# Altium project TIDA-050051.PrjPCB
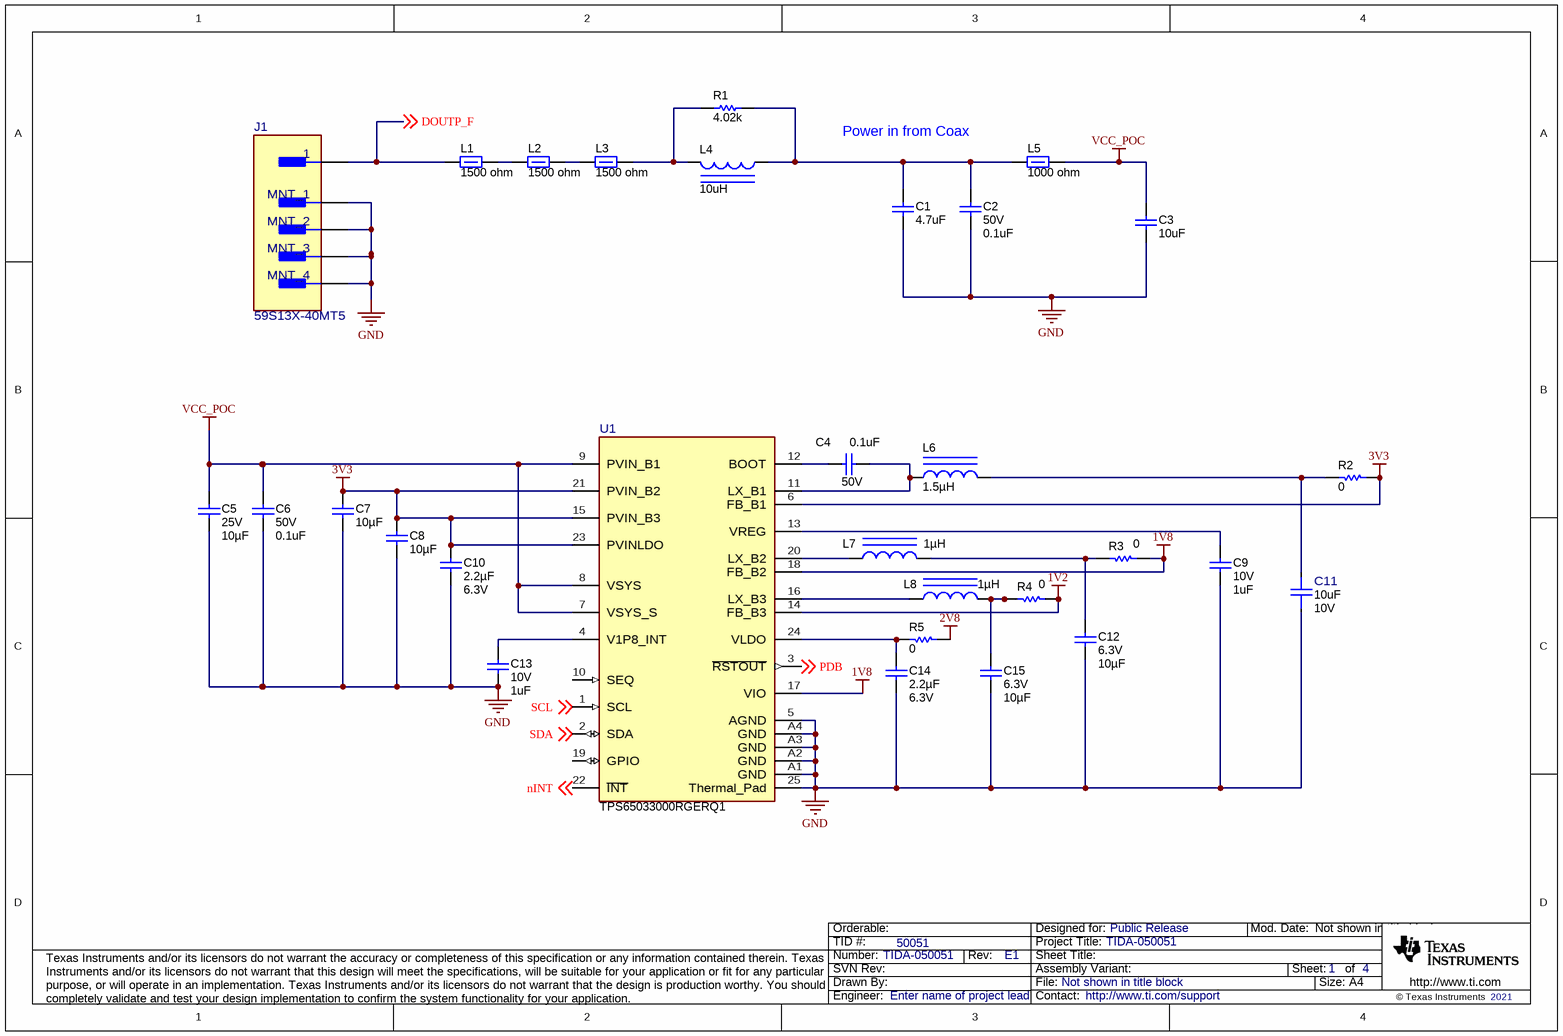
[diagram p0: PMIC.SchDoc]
CopyrightYear: 2021; PCB_Layout: Who did the Layout?; PCB_Rev: E1; PRJ_Customer: Public Release; PRJ_Engineer: Enter name of project lead; PRJ_Number: TIDA-050051; PRJ_Title: TIDA-050051; SCH_Rev: E1; TechSupport: http://www.ti.com/support; TID: 50051
4 sheets, 109 parts. Net scope: global (net labels, ports and power ports of the same name join across sheets).
Board file: TIDA-050051.PcbDoc
Sheets:
  PMIC.SchDoc
  Serializer.SchDoc
  Imager.SchDoc
  Hardware.SchDoc

## Sheet PMIC.SchDoc
size A4; Date: Not shown in title block; ApprovedBy: Not shown in title block; CheckedBy: Not shown in title block; Author: Not shown in title block; CompanyName: Not shown in title block; Engineer: Not shown in title block; Organization: Not shown in title block; Address1: Not shown in title block; Address2: Not shown in title block; Address3: Not shown in title block; Address4: Not shown in title block; DocumentNumber: 1; Revision: Use project parameter SCH_Rev; SheetNumber: 1; SheetTotal: 4; PageSetup: Record=PageOptions¦CenterHorizontal=True¦CenterVertical=True¦PrintScale=1.00¦XCorrection=1.00¦YCorrection=1.00¦PrintKind=0¦BorderSize=5000000¦LeftOffset=0¦BottomOffset=0¦Orientation=2¦PaperLength=1000¦PaperWidth=1000¦Scale=100¦PaperSource=15¦PrintQuality=600¦MediaType=1¦DitherType=10¦PaperKind=Letter¦PrintScaleMode=1

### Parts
C1  ValueDisplayed: 4.7uF  [0805_HV]  (hidden comment: Capacitor)
C2  VDC_V: 50V  ValueDisplayed: 0.1uF  [0402]  (hidden comment: CGA2B3X7R1H104M050BB)
C3  ValueDisplayed: 10uF  [1206_190]  (hidden comment: C3216X7R1E106M160AE)
C4  VDC_V: 50V  ValueDisplayed: 0.1uF  [0402]  (hidden comment: CGA2B3X7R1H104M050BB)
C5  VDC_V: 25V  ValueDisplayed: 10µF  [1206_180]  (hidden comment: C1206C106J3RACAUTO)
C6  VDC_V: 50V  ValueDisplayed: 0.1uF  [0402]  (hidden comment: CGA2B3X7R1H104M050BB)
C7  Cap_F: 10µF  [0603S]  (hidden comment: GRM188Z71A106KA73D)
C8  Cap_F: 10µF  [0603S]  (hidden comment: GRM188Z71A106KA73D)
C9  VDC_V: 10V  ValueDisplayed: 1uF  [0603S]  (hidden comment: LMK107B7105KAHT)
C10  Cap_F: 2.2µF  VDC_V: 6.3V  [0603S]  (hidden comment: GCM188R70J225KE22D)
C11  ValueDisplayed: 10uF  VDC_V: 10V  [FP-CGA4J3X7S1A106K125AE_0805-MFG]  (hidden comment: CGA4J3X7S1A106K125AE)
C12  VDC_V: 6.3V  ValueDisplayed: 10µF  [0805_HV1]  (hidden comment: JMJ212CB7106KGHT)
C13  VDC_V: 10V  ValueDisplayed: 1uF  [0603S]  (hidden comment: LMK107B7105KAHT)
C14  Cap_F: 2.2µF  VDC_V: 6.3V  [0603S]  (hidden comment: GCM188R70J225KE22D)
C15  VDC_V: 6.3V  ValueDisplayed: 10µF  [0805_HV1]  (hidden comment: JMJ212CB7106KGHT)
J1  59S13X-40MT5  [FP-59S13X-40MT5_FAKRA_HF_STR_PLUG-MFG]
L1  value 1500 ohm  [0603L]  (hidden comment: BLM18HE152SN1D)
L2  value 1500 ohm  [0603L]  (hidden comment: BLM18HE152SN1D)
L3  value 1500 ohm  [0603L]  (hidden comment: BLM18HE152SN1D)
L4  ValueDisplayed: 10uH  [LQH3NPZ_JR]  (hidden comment: LQH3NPZ100MJRL)
L5  value 1000 ohm  [0603L]  (hidden comment: BLM18AG102SN1D)
L6  ValueDisplayed: 1.5µH  [TFM201610ALMA]  (hidden comment: TFM201610ALMA1R5MTAA)
L7  ValueDisplayed: 1µH  [TFM201610ALMA]  (hidden comment: TFM201610ALMA1R0MTAA)
L8  ValueDisplayed: 1µH  [TFM201610ALMA]  (hidden comment: TFM201610ALMA1R0MTAA)
R1  ValueDisplayed: 4.02k  [0603L]  (hidden comment: CRCW06034K02FKEA)
R2  ValueDisplayed: 0  [0402S]  (hidden comment: Resistor)
R3  ValueDisplayed: 0  [0402S]  (hidden comment: Resistor)
R4  ValueDisplayed: 0  [0402S]  (hidden comment: Resistor)
R5  ValueDisplayed: 0  [0402S]  (hidden comment: Resistor)
U1  TPS65033000RGERQ1  [RGE0024K-MFG]

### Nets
1V2: R4.2 U1.14(FB_B3)
1V8: R3.2 U1.17(VIO) U1.18(FB_B2)
2V8: R5.2
3V3: C7.1 C8.1 C10.1 R2.2 U1.6(FB_B1) U1.15(PVIN_B3) U1.21(PVIN_B2) U1.23(PVINLDO)
GND: C1.2 C2.2 C3.2 C5.2 C6.2 C7.2 C8.2 C9.1 C10.2 C11.1 C12.2 C13.2 C14.2 C15.2 J1.2(MNT_1) J1.3(MNT_2) J1.4(MNT_3) J1.5(MNT_4) U1.5(AGND) U1.25(Thermal_Pad) U1.A1(GND) U1.A2(GND) U1.A3(GND) U1.A4(GND)
VCC_POC: C3.1 C5.1 C6.1 L5.2 U1.7(VSYS_S) U1.8(VSYS) U1.9(PVIN_B1)
DOUTP_F: J1.1 L1.1 ; off-sheet DOUTP_F
nINT: U1.22(~{INT}) ; off-sheet nINT
PDB: U1.3(~{RSTOUT}) ; off-sheet PDB
SCL: U1.1(SCL) ; off-sheet SCL
SDA: U1.2(SDA) ; off-sheet SDA
NetC1_1: C1.1 C2.1 L4.1 L5.1 R1.1
NetC4_1: C4.1 L6.1 U1.11(LX_B1)
NetC4_2: C4.2 U1.12(BOOT)
NetC9_2: C9.2 U1.13(VREG)
NetC11_2: C11.2 L6.2 R2.1
NetC12_1: C12.1 L7.2 R3.1
NetC13_1: C13.1 U1.4(V1P8_INT)
NetC14_1: C14.1 R5.1 U1.24(VLDO)
NetC15_1: C15.1 L8.2 R4.1
NetL1_2: L1.2 L2.1
NetL2_2: L2.2 L3.1
NetL3_2: L3.2 L4.2 R1.2
NetL7_1: L7.1 U1.20(LX_B2)
NetL8_1: L8.1 U1.16(LX_B3)

Not connected (* = marked no-connect by the designer): U1 10(SEQ) 19(GPIO)

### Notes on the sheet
- (near L5) Power in from Coax

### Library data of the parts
C1 = CMP-0007870-2: CAP, CERM, 4.7 uF, 25 V, +/- 10%, X7R, 0805; PartNumber: C2012X7R1E475K125AB; Manufacturer: TDK; Polarized: N; Value: 4.7uF; U/M: EA; Cap_F: 4.7µF; Value1: Unknown; VDC_V: 25V; TaMin_C: -55°C; TaMax_C: 125°C; Cap_Case: 0805; SizeArea_mm2: 2.5; SizeAreaWB_mm2: 6.75; SizeX_mm: 2; SizeY_mm: 1.25; SizeZ_mm: 1.45; AEC Category: Q200
C2 C4 C6 = CMP-0006326-2: CAP, CERM, 0.1 uF, 50 V, +/- 20%, X7R, AEC-Q200 Grade 1, 0402; Manufacturer: TDK; TaMin_C: -55°C; Polarized: N; SizeAreaWB_mm2: 3; Value1: Unknown; U/M: EA; Value: 0.1uF; TaMax_C: 125°C; SizeZ_mm: 0.6; SizeX_mm: 1; SizeY_mm: 0.5; CompType: Capacitor; AEC Qualified: Y; Cap_F: 100nF; AEC Category: Q200
C3 = CMP-0008692-2: CAP, CERM, 10 uF, 25 V, +/- 20%, X7R, 1206_190; Manufacturer: TDK; Polarized: N; Value: 10uF; U/M: EA; Cap_F: 10µF; Value1: Unknown; VDC_V: 25V; TaMin_C: -55°C; TaMax_C: 125°C; Cap_Case: 1206; SizeArea_mm2: 5.12; SizeAreaWB_mm2: 10.92; SizeX_mm: 3.2; SizeY_mm: 1.6; SizeZ_mm: 1.9; AEC Category: Q200
C5 = CMP-0081062-1: CAP, CERM, 10 µF, 25 V,+/- 5%, X7R, AEC-Q200 Grade 1, 1206; Manufacturer: Kemet; TaMin_C: -55°C; Polarized: N; SizeAreaWB_mm2: 10.92; U/M: EA; Value: 10uF; TaMax_C: 125°C; SizeZ_mm: 1.8; SizeX_mm: 3.2; SizeY_mm: 1.6; SizeArea_mm2: 5.12; AEC Qualified: Y; AEC Grade: 1; AEC Category: Q200
C7 C8 = CMP-0087107-2: Chip Multilayer Ceramic Capacitors for General Purpose; Manufacturer: Murata; Tolerance_%: 10%; VDC_V: 10V; TempCo: 15%; SizeZ_mm: 1mm; AEC Qualified: No
C9 C13 = CMP-0007505-4: CAP, CERM, 1 uF, 10 V, +/- 10%, X7R, AEC-Q200 Grade 1, 0603; Manufacturer: Taiyo Yuden; TaMin_C: -55°C; Polarized: N; SizeAreaWB_mm2: 4.68; Value1: Unknown; U/M: EA; Value: 1uF; TaMax_C: 125°C; SizeZ_mm: 1; SizeX_mm: 1.6; SizeY_mm: 0.8; Cap_Case: 0603; SizeArea_mm2: 1.28; AEC Qualified: Y; Cap_F: 1µF; AEC Category: Q200
C10 C14 = CMP-0007134-5: CAP, CERM, 2.2 uF, 6.3 V, +/- 10%, X7R, AEC-Q200 Grade 1, 0603; Manufacturer: MuRata; SizeAreaWB_mm2: 4.68; Value1: Unknown; Polarized: N; AEC Qualified: Y; SizeX_mm: 1.6; SizeZ_mm: 1; SizeY_mm: 0.8; U/M: EA; TaMin_C: -55°C; Value: 2.2uF; Cap_Case: 0603; AEC Category: Q200; TaMax_C: 125°C; SizeArea_mm2: 1.28
C11 = CMP-0089543-1: 10µF ±10% 10V Ceramic Capacitor X7S 0805 (2012 Metric); Manufacturer: TDK; TempCo: 22%; SizeZ_mm: 1.5mm; AEC Qualified: Yes; AEC Grade: Grade 1
C12 C15 = CMP-0081188-1: CAP, CERM, 10 µF, 6.3 V,+/- 10%, X7R, AEC-Q200 Grade 1, 0805; Manufacturer: Taiyo Yuden; TaMin_C: -55°C; Polarized: N; SizeAreaWB_mm2: 6.75; U/M: EA; Value: 10uF; TaMax_C: 125°C; SizeZ_mm: 1.45; SizeX_mm: 2; SizeY_mm: 1.25; Cap_Case: 0805; SizeArea_mm2: 2.5; AEC Qualified: Y; AEC Category: Q200; AEC Grade: 1
J1 = CMP-0092218-1: FAKRA-HF STRAIGHT PLUG for PCB; Manufacturer: Rosenberger; AEC Qualified: No; ContactFinish: Gold,Tin; Shrouded: true; Dielectric Material: HTN; Voltage_V: 335V; Current_A: 1A; Impedance: 50Ω; SizeZ_mm: 15mm; Frequency_Fixed: 6GHz
L1 L2 = CMP-0003349-2: Ferrite Bead, 1500 ohm @ 100 MHz, 0.5 A, 0603; Manufacturer: MuRata; Imax_A: 500mA; DCR_ohm: 0.5; Value1: 0.5 ohm; Value2: 0.5A; ZTyp@100MHz_Ohm: 1.5k; SizeAreaWB_mm2: 4.68; SizeArea_mm2: 1.28; SizeX_mm: 1.6; SizeY_mm: 0.8; SizeZ_mm: 1
L3 = CMP-0003349-2: Ferrite Bead, 1500 ohm @ 100 MHz, 0.5 A, 0603; Manufacturer: MuRata; Value1: 0.5 ohm; Value2: 0.5A; SizeArea_mm2: 1.28; SizeX_mm: 1.6; SizeY_mm: 0.8; SizeZ_mm: 1; Imax_A: 500mA; DCR_ohm: 0.5; SizeAreaWB_mm2: 4.68; ZTyp@100MHz_Ohm: 1.5k
L4 = CMP-0058702-1: Inductor, Wirewound, Ferrite, 10 uH, 0.81 A, 0.288 ohm, AEC-Q200 Grade 1, SMD; Manufacturer: MuRata; Value: 10uH; Ind_H: 10µH; Imax_A: 810mA; Irms: 1.2A @ 40C rise; Isat: 0.81A @ 30% inductance drop; DCR_ohm: 0.288; Value2: 0.81A; SizeAreaWB_mm2: 16; SizeArea_mm2: 9; SizeX_mm: 3; SizeZ_mm: 1.2; AEC Category: Q200; AEC Qualified: Y; AEC Grade: 1
L5 = CMP-0003343-2: Ferrite Bead, 1000 ohm @ 100 MHz, 0.4 A, 0603; Manufacturer: MuRata; Imax_A: 400mA; DCR_ohm: 0.5; Value1: 0.5 ohm; Value2: 0.4A; ZTyp@100MHz_Ohm: 1k; SizeArea_mm2: 1.28; SizeAreaWB_mm2: 4.68; SizeX_mm: 1.6; SizeY_mm: 0.8; SizeZ_mm: 1
L6 = CMP-0081093-1: Inductor, Shielded, Metal Composite, 1.5 µH, 2.3 A, 0.11 ohm, AEC-Q200 Grade 0, SMD; Manufacturer: TDK; Isat: 2.8A @ 30% inductance drop; Irms: 2.3A @ 40C rise; SizeAreaWB_mm2: 7.8; DCR_ohm: 0.11; Value: 1.5uH; Imax_A: 2.3A; SizeZ_mm: 1; SizeX_mm: 2; SizeY_mm: 1.6; SizeArea_mm2: 3.2; AEC Qualified: Y; AEC Grade: 0; AEC Category: Q200
L7 L8 = CMP-0081092-1: Inductor, Shielded, Metal Composite, 1 µH, 3.1 A, 0.06 ohm, AEC-Q200 Grade 0, SMD; Manufacturer: TDK; Isat: 3.3A @ 30% inductance drop; Irms: 3.1A @ 40C rise; SizeAreaWB_mm2: 7.8; DCR_ohm: 0.06; Value: 1uH; Imax_A: 3.1A; SizeZ_mm: 1; SizeX_mm: 2; SizeY_mm: 1.6; SizeArea_mm2: 3.2; AEC Qualified: Y; AEC Grade: 0; AEC Category: Q200
R1 = CMP-0022449-4: RES, 4.02 k, 1%, 0.1 W, AEC-Q200 Grade 0, 0603; Manufacturer: Vishay-Dale; Value: 4.02k; Value_Code: 4k02; Power_W: 100mW; Value2: 0.1W; VDC_V: 75V; TempCo: 100 ppm/C; EIA_Code: E96; AEC Category: Q200; AEC Grade: 0; AEC Qualified: Y; SizeArea_mm2: 1.28; SizeX_mm: 1.6; SizeY_mm: 0.8; SizeZ_mm: 1
R2-R5 = CMP-0027004-2: RES, 0, 5%, 0.063 W, 0402; PartNumber: RC0402JR-070RL; Manufacturer: Yageo America; Value: 0; Value_Code: 0000; Power_W: 63mW; Value2: 0.063W; VDC_V: 50V; TempCo: 200 ppm/C; SizeArea_mm2: 0.5; SizeX_mm: 1; SizeZ_mm: 0.6; EIA_Code: E24; U/M: EA; AEC Category: Q200
U1 = CMP-0092635-1: Highly integrated power management IC for automotive camera modules; Manufacturer: Texas Instruments; Standoff Height: 0mm; AEC Grade: Grade 1; Output Voltage: 2.5-4/0.9-1.9/1.8-3.3V; Nominal Supply Current: 10mA; Max Supply Voltage: 18.3V; Min Supply Voltage: 4V; TaMin_C: -40°C; TaMax_C: +125°C; AEC Qualified: Yes; SizeZ_mm: 1mm; Number Of Outputs: 4; TJmax_C: +150°C

## Sheet Serializer.SchDoc
size A4; Date: Not shown in title block; ApprovedBy: Not shown in title block; CheckedBy: Not shown in title block; Author: Not shown in title block; CompanyName: Not shown in title block; Engineer: Not shown in title block; Organization: Not shown in title block; Address1: Not shown in title block; Address2: Not shown in title block; Address3: Not shown in title block; Address4: Not shown in title block; DocumentNumber: 2; Revision: Use project parameter SCH_Rev; SheetNumber: 2; SheetTotal: 4; PageSetup: Record=PageOptions¦CenterHorizontal=True¦CenterVertical=True¦PrintScale=1.00¦XCorrection=1.00¦YCorrection=1.00¦PrintKind=0¦BorderSize=5000000¦LeftOffset=0¦BottomOffset=0¦Orientation=2¦PaperLength=1000¦PaperWidth=1000¦Scale=100¦PaperSource=15¦PrintQuality=600¦MediaType=1¦DitherType=10¦PaperKind=Letter¦PrintScaleMode=1
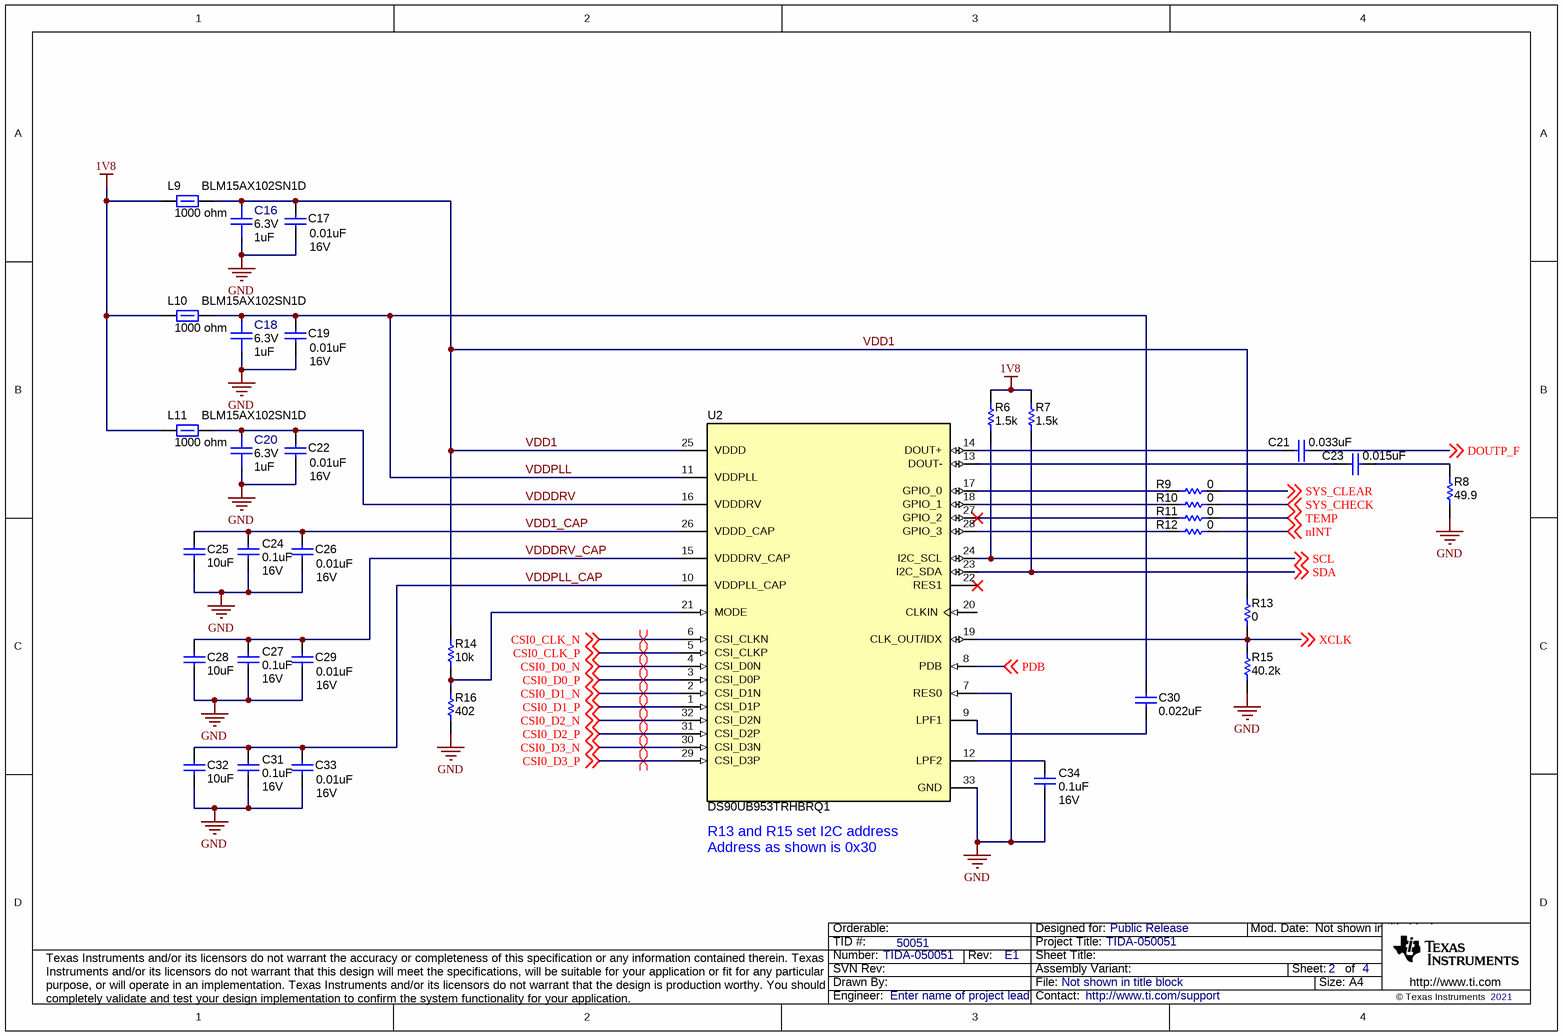
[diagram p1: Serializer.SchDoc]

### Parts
C16  VDC_V: 6.3V  ValueDisplayed: 1uF  [FP-GRT155R70J105KE01D_0402-MFG]  (hidden comment: GRT155R70J105KE01D)
C17  ValueDisplayed: 0.01uF  Value2: 16V  [0402S]  (hidden comment: GRM155R71C103KA01D)
C18  VDC_V: 6.3V  ValueDisplayed: 1uF  [FP-GRT155R70J105KE01D_0402-MFG]  (hidden comment: GRT155R70J105KE01D)
C19  ValueDisplayed: 0.01uF  Value2: 16V  [0402S]  (hidden comment: GRM155R71C103KA01D)
C20  VDC_V: 6.3V  ValueDisplayed: 1uF  [FP-GRT155R70J105KE01D_0402-MFG]  (hidden comment: GRT155R70J105KE01D)
C21  ValueDisplayed: 0.033uF  [0402S]  (hidden comment: CGA2B3X7R1H333K050BB)
C22  ValueDisplayed: 0.01uF  Value2: 16V  [0402S]  (hidden comment: GRM155R71C103KA01D)
C23  ValueDisplayed: 0.015uF  [0402S]  (hidden comment: CGA2B3X7R1H153K050BB)
C24  ValueDisplayed: 0.1uF  Value2: 16V  [0402S]  (hidden comment: 0402YC104KAT2A)
C25  ValueDisplayed: 10uF  [0603S]  (hidden comment: GRM188Z71A106MA73D)
C26  ValueDisplayed: 0.01uF  Value2: 16V  [0402S]  (hidden comment: GRM155R71C103KA01D)
C27  ValueDisplayed: 0.1uF  Value2: 16V  [0402S]  (hidden comment: 0402YC104KAT2A)
C28  ValueDisplayed: 10uF  [0603S]  (hidden comment: GRM188Z71A106MA73D)
C29  ValueDisplayed: 0.01uF  Value2: 16V  [0402S]  (hidden comment: GRM155R71C103KA01D)
C30  ValueDisplayed: 0.022uF  [0402S]  (hidden comment: GRM155R70J223KA01D)
C31  ValueDisplayed: 0.1uF  Value2: 16V  [0402S]  (hidden comment: 0402YC104KAT2A)
C32  ValueDisplayed: 10uF  [0603S]  (hidden comment: GRM188Z71A106MA73D)
C33  ValueDisplayed: 0.01uF  Value2: 16V  [0402S]  (hidden comment: GRM155R71C103KA01D)
C34  ValueDisplayed: 0.1uF  Value2: 16V  [0402S]  (hidden comment: 0402YC104KAT2A)
L9  value 1000 ohm  [0402S]  (hidden comment: BLM15AX102SN1D)
L10  value 1000 ohm  [0402S]  (hidden comment: BLM15AX102SN1D)
L11  value 1000 ohm  [0402S]  (hidden comment: BLM15AX102SN1D)
R6  ValueDisplayed: 1.5k  [0402S]  (hidden comment: CRCW04021K50JNED)
R7  ValueDisplayed: 1.5k  [0402S]  (hidden comment: CRCW04021K50JNED)
R8  value 49.9  [0402L]  (hidden comment: CRCW040249R9FKED)
R9  ValueDisplayed: 0  [0402S]  (hidden comment: CRCW04020000Z0ED)
R10  ValueDisplayed: 0  [0402S]  (hidden comment: CRCW04020000Z0ED)
R11  ValueDisplayed: 0  [0402S]  (hidden comment: CRCW04020000Z0ED)
R12  ValueDisplayed: 0  [0402S]  (hidden comment: CRCW04020000Z0ED)
R13  ValueDisplayed: 0  [0402S]  (hidden comment: CRCW04020000Z0ED)
R14  value 10k  [0402S]  (hidden comment: CRCW040210K0JNED)
R15  ValueDisplayed: 40.2k  [0402S]  (hidden comment: CRCW040240K2FKED)
R16  ValueDisplayed: 402  [0402S]  (hidden comment: CRCW0402402RFKED)
U2  DS90UB953TRHBRQ1  [RHB0032P]

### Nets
1V8: L9.1 L10.1 L11.1 R6.2 R7.2
GND: C16.1 C17.2 C18.1 C19.2 C20.1 C22.2 C24.2 C25.1 C26.2 C27.2 C28.1 C29.2 C31.2 C32.1 C33.2 C34.2 R8.1 R15.1 R16.1 U2.7(RES0) U2.33(GND)
CSI0_CLK_N: U2.6(CSI_CLKN) ; off-sheet CSI0_CLK_N
CSI0_CLK_P: U2.5(CSI_CLKP) ; off-sheet CSI0_CLK_P
CSI0_D0_N: U2.4(CSI_D0N) ; off-sheet CSI0_D0_N
CSI0_D0_P: U2.3(CSI_D0P) ; off-sheet CSI0_D0_P
CSI0_D1_N: U2.2(CSI_D1N) ; off-sheet CSI0_D1_N
CSI0_D1_P: U2.1(CSI_D1P) ; off-sheet CSI0_D1_P
CSI0_D2_N: U2.32(CSI_D2N) ; off-sheet CSI0_D2_N
CSI0_D2_P: U2.31(CSI_D2P) ; off-sheet CSI0_D2_P
CSI0_D3_N: U2.30(CSI_D3N) ; off-sheet CSI0_D3_N
CSI0_D3_P: U2.29(CSI_D3P) ; off-sheet CSI0_D3_P
DOUTP_F: C21.1 ; off-sheet DOUTP_F
nINT: R12.1 ; off-sheet nINT
PDB: U2.8(PDB) ; off-sheet PDB
SCL: R6.1 U2.24(I2C_SCL) ; off-sheet SCL
SDA: R7.1 U2.23(I2C_SDA) ; off-sheet SDA
SYS_CHECK: R10.1 ; off-sheet SYS_CHECK
SYS_CLEAR: R9.1 ; off-sheet SYS_CLEAR
TEMP: R11.1 ; off-sheet TEMP
VDD1: C16.2 C17.1 L9.2 R13.2 R14.2 U2.25(VDDD)
VDD1_CAP: C24.1 C25.2 C26.1 U2.26(VDDD_CAP)
VDDDRV: C20.2 C22.1 L11.2 U2.16(VDDDRV)
VDDDRV_CAP: C27.1 C28.2 C29.1 U2.15(VDDDRV_CAP)
VDDPLL: C18.2 C19.1 C30.1 L10.2 U2.11(VDDPLL)
VDDPLL_CAP: C31.1 C32.2 C33.1 U2.10(VDDPLL_CAP)
XCLK: R13.1 R15.2 U2.19(CLK_OUT/IDX) ; off-sheet XCLK
NetC21_2: C21.2 U2.14(DOUT+)
NetC23_1: C23.1 R8.2
NetC23_2: C23.2 U2.13(DOUT-)
NetC30_2: C30.2 U2.9(LPF1)
NetC34_1: C34.1 U2.12(LPF2)
NetR9_2: R9.2 U2.17(GPIO_0)
NetR10_2: R10.2 U2.18(GPIO_1)
NetR11_2: R11.2 U2.27(GPIO_2)
NetR12_2: R12.2 U2.28(GPIO_3)
NetR14_1: R14.1 R16.2 U2.21(MODE)

Not connected (* = marked no-connect by the designer): U2 20(CLKIN) 22(RES1)*

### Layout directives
differential pair: CSI0_CLK_N, CSI0_CLK_P, CSI0_D0_N, CSI0_D0_P, CSI0_D1_N, CSI0_D1_P, CSI0_D2_N, CSI0_D2_P, CSI0_D3_N, CSI0_D3_P

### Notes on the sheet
- (near U2) R13 and R15 set I2C address
  Address as shown is 0x30

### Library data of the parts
C16 C18 C20 = CMP-0088425-1: 1µF ±10% 6.3V Ceramic Capacitor X7R 0402 (1005 Metric); Manufacturer: Murata; TempCo: 15%; AEC Grade: Grade 1; SizeZ_mm: 0.55mm; AEC Qualified: Yes
C17 C19 C22 C26 C29 C33 = CMP-0006639-2: CAP, CERM, 0.01 uF, 16 V, +/- 10%, X7R, 0402; Manufacturer: MuRata; Polarized: N; Value: 0.01uF; U/M: EA; Cap_F: 10nF; Value1: Unknown; TaMin_C: -55°C; TaMax_C: 125°C; Cap_Case: 0402; AEC Category: Q200; SizeArea_mm2: 0.5; SizeAreaWB_mm2: 3; SizeX_mm: 1; SizeZ_mm: 0.6
C21 = CMP-0006329-2: CAP, CERM, 0.033 uF, 50 V, +/- 10%, X7R, AEC-Q200 Grade 1, 0402; Manufacturer: TDK; Polarized: N; U/M: EA; Cap_F: 33nF; ESR_ohm: 0.098477; Value1: 0.098477 ohm; VDC_V: 50V; IRMS_A: 530.78mA; TaMin_C: -55°C; TaMax_C: 125°C; Cap_Case: 0402; AEC Category: Q200; AEC Grade: 1; AEC Qualified: Y; SizeArea_mm2: 0.5; SizeAreaWB_mm2: 3; SizeZ_mm: 0.6
C23 = CMP-0006327-2: CAP, CERM, 0.015 uF, 50 V, +/- 10%, X7R, AEC-Q200 Grade 1, 0402; Manufacturer: TDK; Polarized: N; U/M: EA; Cap_F: 15nF; ESR_ohm: 0.2162; Value1: 0.2162 ohm; VDC_V: 50V; IRMS_A: 379.389mA; TaMin_C: -55°C; TaMax_C: 125°C; Cap_Case: 0402; SizeArea_mm2: 0.5; SizeAreaWB_mm2: 3; SizeX_mm: 1; SizeZ_mm: 0.6; AEC Category: Q200; AEC Qualified: Y
C24 C27 C31 C34 = CMP-0006201-2: CAP, CERM, 0.1 uF, 16 V, +/- 10%, X7R, 0402; Manufacturer: AVX; Polarized: N; Value: 0.1uF; U/M: EA; Cap_F: 100nF; Value1: Unknown; TaMin_C: -55°C; TaMax_C: 125°C; Cap_Case: 0402; SizeArea_mm2: 0.5; SizeAreaWB_mm2: 3; SizeX_mm: 1; SizeZ_mm: 0.6; AEC Category: Q200
C25 C28 C32 = CMP-0007497-5: CAP, CERM, 10 uF, 10 V, +/- 20%, X7R, 0603; Manufacturer: MuRata; Polarized: N; Value: 10uF; U/M: EA; Cap_F: 10µF; Value1: Unknown; VDC_V: 10V; TaMin_C: -55°C; TaMax_C: 125°C; Cap_Case: 0603; SizeArea_mm2: 1.28; SizeAreaWB_mm2: 4.68; SizeX_mm: 1.6; SizeY_mm: 0.8; SizeZ_mm: 1; AEC Category: Q200
C30 = CMP-0006626-2: CAP, CERM, 0.022 uF, 6.3 V, +/- 10%, X7R, 0402; Manufacturer: MuRata; Polarized: N; U/M: EA; Cap_F: 22nF; Value1: Unknown; VDC_V: 6.3V; TaMin_C: -55°C; TaMax_C: 125°C; Cap_Case: 0402; SizeArea_mm2: 0.5; SizeAreaWB_mm2: 3; SizeX_mm: 1; SizeZ_mm: 0.6; AEC Category: Q200
L9-L11 = CMP-0003316-1: Ferrite Bead, 1000 ohm @ 100 MHz, 0.35 A, 0402; Manufacturer: MuRata; Imax_A: 350mA; DCR_ohm: 0.49; Value1: 0.49 ohm; Value2: 0.35A; ZTyp@100MHz_Ohm: 1k; SizeArea_mm2: 0.5; SizeAreaWB_mm2: 3; SizeX_mm: 1; SizeZ_mm: 0.6
R6 R7 = CMP-0026856-5: RES, 1.5 k, 5%, 0.063 W, AEC-Q200 Grade 0, 0402; Manufacturer: Vishay-Dale; Value: 1.5k; Value_Code: 1k50; Power_W: 63mW; Value2: 0.063W; VDC_V: 50V; TempCo: 200 ppm/C; SizeArea_mm2: 0.5; SizeX_mm: 1; SizeZ_mm: 0.6; EIA_Code: E24; AEC Category: Q200; AEC Qualified: Y; AEC Grade: 0
R8 = CMP-0026404-2: RES, 49.9, 1%, 0.063 W, AEC-Q200 Grade 0, 0402; Manufacturer: Vishay-Dale; Value_Code: 49R9; Power_W: 63mW; Value2: 0.063W; VDC_V: 50V; TempCo: 100 ppm/C; EIA_Code: E96; AEC Category: Q200; AEC Grade: 0; AEC Qualified: Y; SizeArea_mm2: 0.5; SizeX_mm: 1; SizeZ_mm: 0.6
R9-R13 = CMP-0026822-3: RES, 0, 5%, 0.063 W, AEC-Q200 Grade 0, 0402; Manufacturer: Vishay-Dale; Value: 0; Value_Code: 0000; Power_W: 63mW; Value2: 0.063W; VDC_V: 50V; TempCo: 200 ppm/C; SizeArea_mm2: 0.5; SizeX_mm: 1; SizeZ_mm: 0.6; EIA_Code: E24; AEC Category: Q200; AEC Qualified: Y
R14 = CMP-0026825-5: RES, 10 k, 5%, 0.063 W, AEC-Q200 Grade 0, 0402; Manufacturer: Vishay-Dale; Value_Code: 10k0; Power_W: 63mW; Value2: 0.063W; VDC_V: 50V; TempCo: 200 ppm/C; EIA_Code: E24; AEC Category: Q200; AEC Grade: 0; AEC Qualified: Y; SizeArea_mm2: 0.5; SizeX_mm: 1; SizeZ_mm: 0.6
R15 = CMP-0026367-2: RES, 40.2 k, 1%, 0.063 W, AEC-Q200 Grade 0, 0402; Manufacturer: Vishay-Dale; Value: 40.2k; Value_Code: 40k2; Power_W: 63mW; Value2: 0.063W; VDC_V: 50V; TempCo: 100 ppm/C; SizeArea_mm2: 0.5; SizeX_mm: 1; SizeZ_mm: 0.6; EIA_Code: E96; AEC Category: Q200; AEC Qualified: Y; AEC Grade: 0
R16 = CMP-0026366-2: RES, 402, 1%, 0.063 W, AEC-Q200 Grade 0, 0402; Manufacturer: Vishay-Dale; Value: 402; Value_Code: 402R; Power_W: 63mW; Value2: 0.063W; VDC_V: 50V; TempCo: 100 ppm/C; SizeArea_mm2: 0.5; SizeX_mm: 1; SizeZ_mm: 0.6; EIA_Code: E96; AEC Category: Q200; AEC Qualified: Y; AEC Grade: 0
U2 = CMP-0084098-1: 2MP MIPI CSI-2 FPD-Link III Serializer for 2MP/60fps Cameras and RADAR, RHB0032P (VQFN-32); Manufacturer: Texas Instruments; Alternate PartNumber: DS90UB953TRHBTQ1; Rating: Automotive; SizeAreaWB_mm2: 49; SizeArea_mm2: 25; AEC Qualified: Y; AEC Category: Q200; SizeZ_mm: 1; SizeY_mm: 5; CompType: IC

## Sheet Imager.SchDoc
size A4; Date: Not shown in title block; ApprovedBy: Not shown in title block; CheckedBy: Not shown in title block; Author: Not shown in title block; CompanyName: Not shown in title block; Engineer: Not shown in title block; Organization: Not shown in title block; Address1: Not shown in title block; Address2: Not shown in title block; Address3: Not shown in title block; Address4: Not shown in title block; DocumentNumber: 3; Revision: Use project parameter SCH_Rev; SheetNumber: 3; SheetTotal: 4; PageSetup: Record=PageOptions¦CenterHorizontal=True¦CenterVertical=True¦PrintScale=1.00¦XCorrection=1.00¦YCorrection=1.00¦PrintKind=0¦BorderSize=5000000¦LeftOffset=0¦BottomOffset=0¦Orientation=2¦PaperLength=1000¦PaperWidth=1000¦Scale=100¦PaperSource=15¦PrintQuality=600¦MediaType=1¦DitherType=10¦PaperKind=Letter¦PrintScaleMode=1
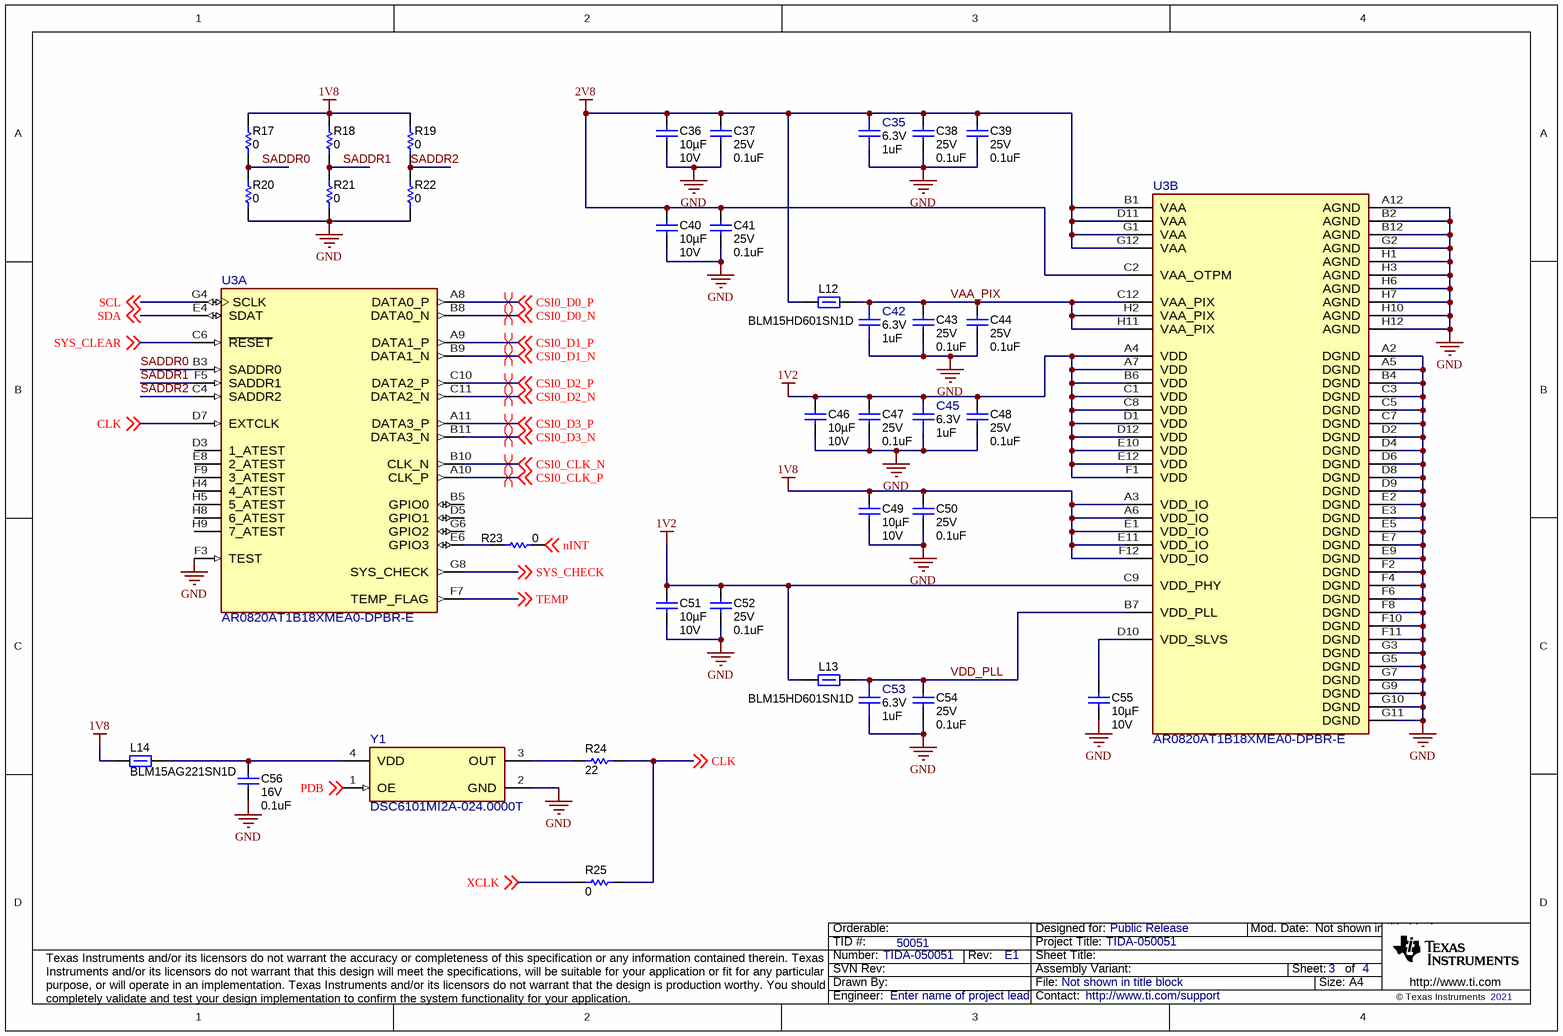
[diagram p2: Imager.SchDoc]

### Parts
C35  VDC_V: 6.3V  ValueDisplayed: 1uF  [FP-GRT155R70J105KE01D_0402-MFG]  (hidden comment: GRT155R70J105KE01D)
C36  Cap_F: 10µF  VDC_V: 10V  [0805_HV1]  (hidden comment: GCJ21BR71A106KE01L)
C37  VDC_V: 25V  ValueDisplayed: 0.1uF  [0402L]  (hidden comment: GRM155R71E104KE14D)
C38  VDC_V: 25V  ValueDisplayed: 0.1uF  [0402L]  (hidden comment: GRM155R71E104KE14D)
C39  VDC_V: 25V  ValueDisplayed: 0.1uF  [0402L]  (hidden comment: GRM155R71E104KE14D)
C40  Cap_F: 10µF  VDC_V: 10V  [0805_HV1]  (hidden comment: GCJ21BR71A106KE01L)
C41  VDC_V: 25V  ValueDisplayed: 0.1uF  [0402L]  (hidden comment: GRM155R71E104KE14D)
C42  VDC_V: 6.3V  ValueDisplayed: 1uF  [FP-GRT155R70J105KE01D_0402-MFG]  (hidden comment: GRT155R70J105KE01D)
C43  VDC_V: 25V  ValueDisplayed: 0.1uF  [0402L]  (hidden comment: GRM155R71E104KE14D)
C44  VDC_V: 25V  ValueDisplayed: 0.1uF  [0402L]  (hidden comment: GRM155R71E104KE14D)
C45  VDC_V: 6.3V  ValueDisplayed: 1uF  [FP-GRT155R70J105KE01D_0402-MFG]  (hidden comment: GRT155R70J105KE01D)
C46  Cap_F: 10µF  VDC_V: 10V  [0805_HV1]  (hidden comment: GCJ21BR71A106KE01L)
C47  VDC_V: 25V  ValueDisplayed: 0.1uF  [0402L]  (hidden comment: GRM155R71E104KE14D)
C48  VDC_V: 25V  ValueDisplayed: 0.1uF  [0402L]  (hidden comment: GRM155R71E104KE14D)
C49  Cap_F: 10µF  VDC_V: 10V  [0805_HV1]  (hidden comment: GCJ21BR71A106KE01L)
C50  VDC_V: 25V  ValueDisplayed: 0.1uF  [0402L]  (hidden comment: GRM155R71E104KE14D)
C51  Cap_F: 10µF  VDC_V: 10V  [0805_HV1]  (hidden comment: GCJ21BR71A106KE01L)
C52  VDC_V: 25V  ValueDisplayed: 0.1uF  [0402L]  (hidden comment: GRM155R71E104KE14D)
C53  VDC_V: 6.3V  ValueDisplayed: 1uF  [FP-GRT155R70J105KE01D_0402-MFG]  (hidden comment: GRT155R70J105KE01D)
C54  VDC_V: 25V  ValueDisplayed: 0.1uF  [0402L]  (hidden comment: GRM155R71E104KE14D)
C55  Cap_F: 10µF  VDC_V: 10V  [0805_HV1]  (hidden comment: GCJ21BR71A106KE01L)
C56  VDC_V: 16V  ValueDisplayed: 0.1uF  [0402S]  (hidden comment: GCM155R71C104KA55D)
L12  BLM15HD601SN1D  [0402S]
L13  BLM15HD601SN1D  [0402S]
L14  BLM15AG221SN1D  [0402S]
R17  ValueDisplayed: 0  [0402S]  (hidden comment: CRCW04020000Z0ED)
R18  ValueDisplayed: 0  [0402S]  (hidden comment: CRCW04020000Z0ED)
R19  ValueDisplayed: 0  [0402S]  (hidden comment: CRCW04020000Z0ED)
R20  ValueDisplayed: 0  [0402S]  (hidden comment: CRCW04020000Z0ED)
R21  ValueDisplayed: 0  [0402S]  (hidden comment: CRCW04020000Z0ED)
R22  ValueDisplayed: 0  [0402S]  (hidden comment: CRCW04020000Z0ED)
R23  ValueDisplayed: 0  [0402S]  (hidden comment: CRCW04020000Z0ED)
R24  ValueDisplayed: 22  [0402S]  (hidden comment: ERJ-2GEJ220X)
R25  ValueDisplayed: 0  [0402S]  (hidden comment: ERJ-2GE0R00X)
U3  AR0820AT1B18XMEA0-DPBR-E  [FP-AR0820AT1B18XMEA0-DPBR-E_iBGA95-MFG]  (parts A,B of 2)
Y1  DSC6101MI2A-024.0000T  [FP-DSC6101MI2A-024.0000T_VFLGA4-0]

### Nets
1V2: C45.2 C46.1 C47.1 C48.1 C51.1 C52.1 L13.1 U3.A4(VDD) U3.A7(VDD) U3.B6(VDD) U3.C1(VDD) U3.C8(VDD) U3.C9(VDD_PHY) U3.D1(VDD) U3.D12(VDD) U3.E10(VDD) U3.E12(VDD) U3.F1(VDD)
1V8: C49.1 C50.1 L14.1 R17.2 R18.2 R19.2 U3.A3(VDD_IO) U3.A6(VDD_IO) U3.E1(VDD_IO) U3.E11(VDD_IO) U3.F12(VDD_IO)
2V8: C35.2 C36.1 C37.1 C38.1 C39.1 C40.1 C41.1 L12.1 U3.B1(VAA) U3.C2(VAA_OTPM) U3.D11(VAA) U3.G1(VAA) U3.G12(VAA)
GND: C35.1 C36.2 C37.2 C38.2 C39.2 C40.2 C41.2 C42.1 C43.2 C44.2 C45.1 C46.2 C47.2 C48.2 C49.2 C50.2 C51.2 C52.2 C53.1 C54.2 C55.2 C56.2 R20.1 R21.1 R22.1 U3.A2(DGND) U3.A5(DGND) U3.A12(AGND) U3.B2(AGND) U3.B4(DGND) U3.B12(AGND) U3.C3(DGND) U3.C5(DGND) U3.C7(DGND) U3.D2(DGND) U3.D4(DGND) U3.D6(DGND) U3.D8(DGND) U3.D9(DGND) U3.E2(DGND) U3.E3(DGND) U3.E5(DGND) U3.E7(DGND) U3.E9(DGND) U3.F2(DGND) U3.F3(TEST) U3.F4(DGND) U3.F6(DGND) U3.F8(DGND) U3.F10(DGND) U3.F11(DGND) U3.G2(AGND) U3.G3(DGND) U3.G5(DGND) U3.G7(DGND) U3.G9(DGND) U3.G10(DGND) U3.G11(DGND) U3.H1(AGND) U3.H3(AGND) U3.H6(AGND) U3.H7(AGND) U3.H10(AGND) U3.H12(AGND) Y1.2(GND)
CLK: R24.2 R25.2 U3.D7(EXTCLK) ; off-sheet CLK
CSI0_CLK_N: U3.B10(CLK_N) ; off-sheet CSI0_CLK_N
CSI0_CLK_P: U3.A10(CLK_P) ; off-sheet CSI0_CLK_P
CSI0_D0_N: U3.B8(DATA0_N) ; off-sheet CSI0_D0_N
CSI0_D0_P: U3.A8(DATA0_P) ; off-sheet CSI0_D0_P
CSI0_D1_N: U3.B9(DATA1_N) ; off-sheet CSI0_D1_N
CSI0_D1_P: U3.A9(DATA1_P) ; off-sheet CSI0_D1_P
CSI0_D2_N: U3.C11(DATA2_N) ; off-sheet CSI0_D2_N
CSI0_D2_P: U3.C10(DATA2_P) ; off-sheet CSI0_D2_P
CSI0_D3_N: U3.B11(DATA3_N) ; off-sheet CSI0_D3_N
CSI0_D3_P: U3.A11(DATA3_P) ; off-sheet CSI0_D3_P
nINT: R23.1 ; off-sheet nINT
PDB: Y1.1(OE) ; off-sheet PDB
SADDR0: R17.1 R20.2 U3.B3(SADDR0)
SADDR1: R18.1 R21.2 U3.F5(SADDR1)
SADDR2: R19.1 R22.2 U3.C4(SADDR2)
SCL: U3.G4(SCLK) ; off-sheet SCL
SDA: U3.E4(SDAT) ; off-sheet SDA
SYS_CHECK: U3.G8(SYS_CHECK) ; off-sheet SYS_CHECK
SYS_CLEAR: U3.C6(~{RESET}) ; off-sheet SYS_CLEAR
TEMP: U3.F7(TEMP_FLAG) ; off-sheet TEMP
VAA_PIX: C42.2 C43.1 C44.1 L12.2 U3.C12(VAA_PIX) U3.H2(VAA_PIX) U3.H11(VAA_PIX)
VDD_PLL: C53.2 C54.1 L13.2 U3.B7(VDD_PLL)
XCLK: R25.1 ; off-sheet XCLK
NetC55_1: C55.1 U3.D10(VDD_SLVS)
NetC56_1: C56.1 L14.2 Y1.4(VDD)
NetR23_2: R23.2 U3.E6(GPIO3)
NetR24_1: R24.1 Y1.3(OUT)

Not connected (* = marked no-connect by the designer): U3 B5(GPIO0) D3(1_ATEST) D5(GPIO1) E8(2_ATEST) F9(3_ATEST) G6(GPIO2) H4(4_ATEST) H5(5_ATEST) H8(6_ATEST) H9(7_ATEST)

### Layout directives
differential pair: CSI0_CLK_N, CSI0_CLK_P, CSI0_D0_N, CSI0_D0_P, CSI0_D1_N, CSI0_D1_P, CSI0_D2_N, CSI0_D2_P, CSI0_D3_N, CSI0_D3_P

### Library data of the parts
C35 C42 C45 C53 = CMP-0088425-1: as C16 on sheet Serializer
C36 C40 C46 C49 C51 C55 = CMP-0079153-1: CAP, CERM, 10 µF, 10 V,+/- 10%, X7R, AEC-Q200 Grade 1, 0805; Manufacturer: MuRata; SizeAreaWB_mm2: 6.75; SizeArea_mm2: 2.5; AEC Qualified: Y; AEC Category: Q200; Value: 10uF; TaMax_C: 125°C; SizeZ_mm: 1.45; AEC Grade: 1; Polarized: N; TaMin_C: -55°C; SizeY_mm: 1.25; U/M: EA; SizeX_mm: 2; Cap_Case: 0805
C37-C39 C41 C43 C44 C47 C48 C50 C52 C54 = CMP-0006659-2: CAP, CERM, 0.1 uF, 25 V, +/- 10%, X7R, 0402; Manufacturer: MuRata; TaMin_C: -55°C; Polarized: N; SizeAreaWB_mm2: 3; Value1: Unknown; U/M: EA; Value: 0.1uF; TaMax_C: 125°C; SizeZ_mm: 0.6; SizeX_mm: 1; SizeY_mm: 0.5; Cap_Case: 0402; CompType: Capacitor; Cap_F: 100nF; AEC Category: Q200
C56 = CMP-0006351-2: CAP, CERM, 0.1 uF, 16 V, +/- 10%, X7R, 0402; Manufacturer: MuRata; TaMin_C: -55°C; Polarized: N; SizeAreaWB_mm2: 3; Value1: Unknown; U/M: EA; Value: 0.1uF; TaMax_C: 125°C; SizeZ_mm: 0.6; SizeX_mm: 1; SizeY_mm: 0.5; Cap_Case: 0402; Cap_F: 100nF; AEC Category: Q200
L12 L13 = CMP-0084741-1: Ferrite Bead, 600 ohm @ 100 MHz, 0.3 A, 0402; Manufacturer: MuRata; SizeZ_mm: 0.6; DCR_ohm: 0.95; Value1: 0.95 ohm; ValueDisplayed: 600 ohm; Value: 600 ohm; Value2: 0.3A; SizeX_mm: 1; SizeY_mm: 0.5; Ztyp@1GHz_Ohm: 1.4k; Imax_A: 300mA; SizeAreaWB_mm2: 3; ZTyp@100MHz_Ohm: 600
L14 = CMP-0003312-1: Ferrite Bead, 220 ohm @ 100 MHz, 0.45 A, 0402; Manufacturer: MuRata; ZTyp@100MHz_Ohm: 220; SizeAreaWB_mm2: 3; DCR_ohm: 0.29; Value1: 0.29 ohm; Value: 220 ohm; Imax_A: 450mA; SizeZ_mm: 0.6; SizeX_mm: 1; SizeY_mm: 0.5; Value2: 0.45A
R17-R23 = CMP-0026822-3: as R9 on sheet Serializer
R24 = CMP-0026997-2: RES, 22, 5%, 0.1 W, AEC-Q200 Grade 0, 0402; Manufacturer: Panasonic; Power_W: 100mW; TempCo: 200 ppm/C; Value_Code: 22R0; U/M: EA; Value: 22; EIA_Code: E24; SizeX_mm: 1; SizeY_mm: 0.5; SizeZ_mm: 0.6; Value2: 0.1W; AEC Qualified: Y; AEC Grade: 0; AEC Category: Q200
R25 = CMP-0026992-3: RES, 0, 5%, 0.1 W, AEC-Q200 Grade 0, 0402; Manufacturer: Panasonic; Power_W: 100mW; TempCo: 600 ppm/C; Value_Code: 0000; Value: 0; EIA_Code: E24; SizeX_mm: 1; SizeY_mm: 0.5; SizeZ_mm: 0.6; Value2: 0.1W; AEC Qualified: Y; VDC_V: 50V; AEC Category: Q200; SizeAreaWB_mm2: 3
U3 = CMP-0092734-1: CMOS Image Sensor, Digital, 8.3 MP, 1/2-inch, High-Resolution; Manufacturer: On Semiconductor; TJmax_C: +125°C; Max Supply Voltage: 3V; Min Supply Voltage: 1.14V; TaMax_C: +105°C; SizeZ_mm: 1.875mm; AEC Qualified: No; Standoff Height: 0.35mm; TaMin_C: -40°C; Sensor Output: Other; Operating Supply Current: 1500mA
Y1 = CMP-0087863-1: MEMS OSC XO 24.0000MHZ CMOS SMD; Manufacturer: Microchip; TaMax_C: 85°C; TaMin_C: -40°C; AEC Qualified: No; Frequency Stability: 25ppm; SizeZ_mm: 0.89mm; Frequency_Fixed: 24MHz

## Sheet Hardware.SchDoc
size 431 x 279 mm; Date: Not shown in title block; ApprovedBy: Not shown in title block; CheckedBy: Not shown in title block; Author: Not shown in title block; CompanyName: Not shown in title block; Engineer: Not shown in title block; Organization: Not shown in title block; Address1: Not shown in title block; Address2: Not shown in title block; Address3: Not shown in title block; Address4: Not shown in title block; DocumentNumber: 4; Revision: Use project parameter SCH_Rev; SheetNumber: 4; SheetTotal: 4; PageSetup: Record=PageOptions¦CenterHorizontal=True¦CenterVertical=True¦PrintScale=1.00¦XCorrection=1.00¦YCorrection=1.00¦PrintKind=0¦BorderSize=5000000¦LeftOffset=0¦BottomOffset=0¦Orientation=2¦PaperLength=1000¦PaperWidth=1000¦Scale=100¦PaperSource=15¦PrintQuality=600¦MediaType=1¦DitherType=10¦PaperKind=Letter¦PrintScaleMode=1
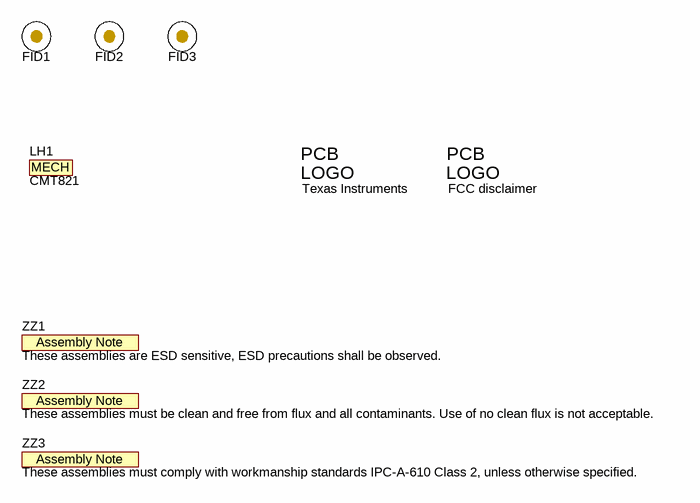
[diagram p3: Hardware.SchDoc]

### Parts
FID1  Fiducial  [Fiducial10-20]  (value not drawn)
FID2  Fiducial  [Fiducial10-20]  (value not drawn)
FID3  Fiducial  [Fiducial10-20]  (value not drawn)
LH1  CMT821  [CMT821]
Logo1  Texas Instruments  [TI_Symbol_Overlay_Small]  (no BOM)
Logo2  FCC disclaimer  [FCC_disclaimer]  (no BOM)
ZZ1  These assemblies are ESD sensitive, ESD precautions shall be observed.  [AssemblyNote]  (no BOM)
ZZ2  These assemblies must be clean and free from flux and all contaminants. Use of no clean flux is not acceptable.  [AssemblyNote]  (no BOM)
ZZ3  These assemblies must comply with workmanship standards IPC-A-610 Class 2, unless otherwise specified.  [AssemblyNote]  (no BOM)

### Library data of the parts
FID1-FID3 = CMP-0077181-1: Fiducial mark.  There is nothing to buy or mount.
LH1 = CMT821: Sunex Lens Holder; Manufacturer: Sunex Inc.
Logo1 = CMP-0074838-1: Texas Instrument Corporate Signature; SymbolCreator: a0412235; Lib Reference: TI_Logo; Library Reference: Logo
Logo2 = CMP-0074847-1: FCC_disclaimer; Library Reference: Logo
ZZ1 = CMP-0077236-1
ZZ2 = CMP-0077237-1
ZZ3 = CMP-0077238-1

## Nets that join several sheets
1V2: PMIC (R4.2 U1.14), Imager (18 pins)
1V8: PMIC (R3.2 U1.17 U1.18), Serializer (5 pins), Imager (11 pins)
2V8: PMIC (R5.2), Imager (13 pins)
GND: PMIC (24 pins), Serializer (21 pins), Imager (65 pins)
CSI0_CLK_N: Serializer (U2.6), Imager (U3.B10)
CSI0_CLK_P: Serializer (U2.5), Imager (U3.A10)
CSI0_D0_N: Serializer (U2.4), Imager (U3.B8)
CSI0_D0_P: Serializer (U2.3), Imager (U3.A8)
CSI0_D1_N: Serializer (U2.2), Imager (U3.B9)
CSI0_D1_P: Serializer (U2.1), Imager (U3.A9)
CSI0_D2_N: Serializer (U2.32), Imager (U3.C11)
CSI0_D2_P: Serializer (U2.31), Imager (U3.C10)
CSI0_D3_N: Serializer (U2.30), Imager (U3.B11)
CSI0_D3_P: Serializer (U2.29), Imager (U3.A11)
DOUTP_F: PMIC (J1.1 L1.1), Serializer (C21.1)
nINT: PMIC (U1.22), Serializer (R12.1), Imager (R23.1)
PDB: PMIC (U1.3), Serializer (U2.8), Imager (Y1.1)
SCL: PMIC (U1.1), Serializer (R6.1 U2.24), Imager (U3.G4)
SDA: PMIC (U1.2), Serializer (R7.1 U2.23), Imager (U3.E4)
SYS_CHECK: Serializer (R10.1), Imager (U3.G8)
SYS_CLEAR: Serializer (R9.1), Imager (U3.C6)
TEMP: Serializer (R11.1), Imager (U3.F7)
XCLK: Serializer (R13.1 R15.2 U2.19), Imager (R25.1)

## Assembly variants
001: not fitted FID1 FID2 FID3 J1 R10 R11 R12 R13 R17 R18 R19 R23 R25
